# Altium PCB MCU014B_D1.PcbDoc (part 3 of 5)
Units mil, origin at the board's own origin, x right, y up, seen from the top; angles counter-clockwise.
Board outline 2300.04 x 4058 mil, 4 copper layers (TOP, GND, PWR, BOTTOM), stack 48.84 mil thick; 371 components, 238 nets, 1148 pads, 688 vias.
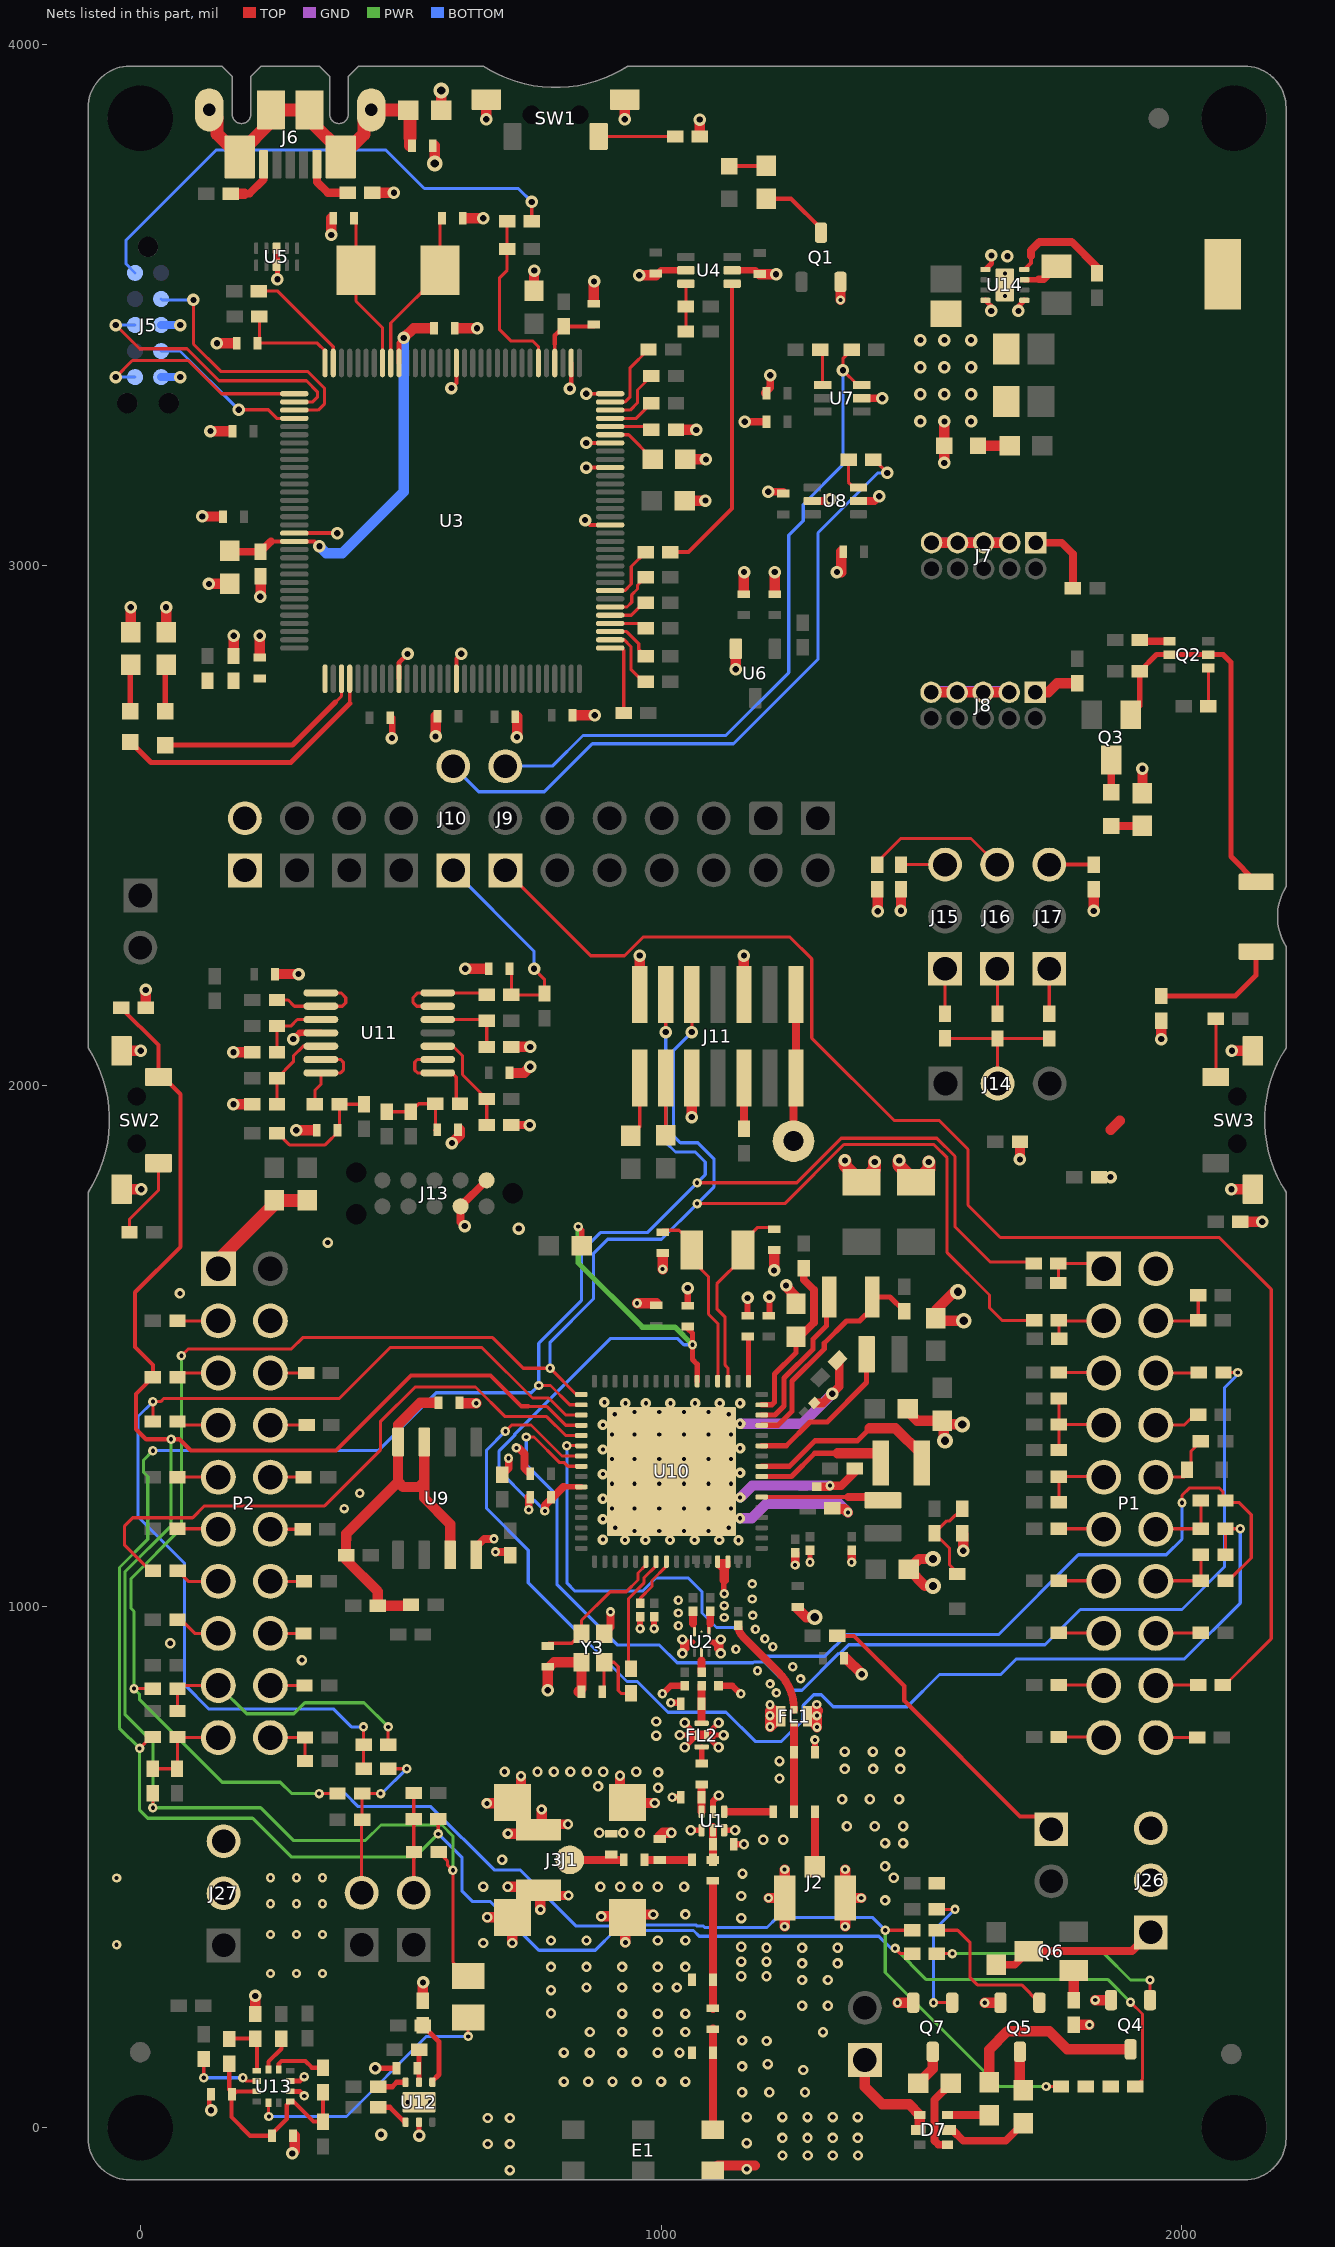
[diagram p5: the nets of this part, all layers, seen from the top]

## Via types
v1: diameter 24, hole 12, TOP to BOTTOM, tented both sides, 230 vias
v2: diameter 18, hole 8, TOP to BOTTOM, tented both sides, 218 vias
v3: diameter 20, hole 10, TOP to BOTTOM, tented both sides, 159 vias
v4: diameter 19.68, hole 7.87, TOP to BOTTOM, 32 vias
v5: diameter 20, hole 8, TOP to BOTTOM, tented both sides, 24 vias
v6: diameter 30, hole 16, TOP to BOTTOM, tented both sides, 17 vias
v7: diameter 20, hole 8, TOP to BOTTOM, tented bottom, 4 vias
v8: diameter 19.68, hole 7.87, TOP to BOTTOM, tented bottom, 4 vias

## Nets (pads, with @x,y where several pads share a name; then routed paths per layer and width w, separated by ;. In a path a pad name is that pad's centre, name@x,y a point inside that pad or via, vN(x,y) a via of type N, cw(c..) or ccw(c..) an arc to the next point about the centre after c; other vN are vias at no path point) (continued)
GND: C3.2 C4.2 C5.2 C8.2 C11.2 C14.2 C15.2 C17.2 C18.2 C19.2 C20.2 C21.1 C22.2 C23.1 C24.2 C25.2 C26.2 C27.2 C28.2 C29.2 C30.2 C31.2 C32.2 C33.2 C34.2 C35.2 C36.2 C37.2 C38.2 C39.2 C40.2 C41.2 C42.2 C43.2 C44.2 C45.2 C46.2 C47.2 C48.2 C49.2 C50.2 C51.2 C52.2 C53.2 C54.2 C55.2 C56.2 C57.2 C58.2 C59.2 C60.2 C61.2 C62.2 C63.2 C64.2 C65.2 C66.2 C67.2 C68.2 C69.2 C70.2 C71.2 C72.2 C73.2 C74.2 C75.2 C76.2 C77.2 C78.2 C79.2 C80.2 C81.2 C82.2 D8.1 E1.1 E1.6 FL1.2 FL1.4 FL2.2 J1.2 J1.3 J1.4 J1.5 J2.2@1353.38,440.99 J2.3@1237.23,440.99 J3.2@764.84,456.14 J3.3@764.84,572.28 J5.3 J5.5 J7.3 J7.5 J7.7 J7.9 J8.3 J8.5 J8.7 J8.9 J11.5 J11.10 J11.13 J13.1 J13.9 J26.2 J26.3 J27.2 J27.3 J28.1 J28.2 L1.2 L2.2 L3.1 L3.2 L4.1 L6.2 P1.2 P2.4 Q1.2 Q4.2 Q5.2 Q7.2 R16.1 R18.1 R19.1 R21.1 R25.1 R27.1 R30.1 R45.2 R46.2 R56.2 R57.2 R58.2 R59.2 R62.2 R63.2 R118.1 R119.1 R128.1 R129.1 R140.1 R144.1 R156.2 R157.2 R158.1 R159.1 R169.2 R170.2 R171.2 R172.1 SW1.1 SW1.2 SW2.1 SW2.2 SW3.1 SW3.2 TP2.1 U1.2 U1.4 U1.6 U2.2 U3.10 U3.17 U3.48 U3.55 U3.58 U3.64 U3.66 U3.80 U3.114 U4.2 U4.5 U5.3@261.87,3608.55 U5.8@261.87,3575.68 U6.2 U7.2 U8.2 U8.5 U9.4 U10.29 U10.30 U10.65@1020,1260 U11.11 U12.2 U12.7@535.13,48.96 U13.8 U13.9 U14.1 U14.4 U14.5 U14.9@1660,3538 Y3.2 Y3.4 | length 9418.8
  TOP w6: v1(856.09,3329.09) U3.64@902.15,3329.09
  TOP w7.5: U3.114@295.85,3061.38 v1(378.38,3061.38) ; v1(597.5,3340) 606.87,3349.37 U3.80@606.87,3388.15 ; U3.17@606.87,2781.85 606.87,2820.63 v1(616.24,2830) ; v1(854,3086.5) 863.37,3077.13 U3.48@902.15,3077.13
  TOP w8: C77.2@132.38,64.62 132.38,37.24 v1(136,33.62) ; v1(856.09,3187.36) U3.55@902.15,3187.36 ; v1(856.09,3234.61) U3.58@902.15,3234.61
  TOP w9: U3.10@496.64,2781.85 496.64,2812.72 v1(513.33,2829.41) ; v1(825,3339) 827.35,3341.35 U3.66@827.35,3388.15
  TOP w10: U5.3@261.87,3608.85 263.37,3607.35 v1(263.37,3548.7) ; U13.8@288.09,69.78 306.16,69.78 v2(314.75,61.18) ; U13.9@288.09,89.46 306.16,89.46 v2(314.75,98.06) ; v1@451.39,114.17 C75.2@488.19,114.17 ; v1@535.13,-14.51 U12.2@535.13,10.58 ; U10.65@1020,1260 U10.65@1060.07,1260 ; v3(1035.72,753.95) 1056.53,753.95 ; v3(1045.23,730.26) 1056.61,741.64 ; v3(1045.23,777.49) 1056.61,766.11 ; v3(1056.95,571.21) U1.4@1077.81,571.21 ; 1060.99,932.29 1055.82,932.29 ; 1094.62,932.29 1099.79,932.29 ; v3(1110.38,730.26) 1099,741.64 ; v3(1110.38,777.49) 1099,766.11 ; v3(1119.89,753.79) 1099.08,753.79 1099,753.87 ; v2@1120.3,1026.4 1120.3,1044.53 ; U1.6@1121.11,571.21 v3(1141.97,571.21) ; v2(1285.88,1085.78) C55.2@1285.88,1108.75 ; U14.4@1622.6,3508.47 1634,3497.07 v1(1634,3488) ; U14.1@1622.6,3567.53 1634.17,3579.09 v1(1634.17,3594.56) ; v1(1686,3488) 1686,3497.07 U14.5@1697.4,3508.47 ; 1055.82,932.29 1045.97,932.29 v3(1040.92,937.34) v3(1040.92,910.62) 1049.27,918.97 1049.27,925.75 1055.82,932.29 ; 1056.61,741.64 FL2.2@1068.85,753.87 ; 1056.61,741.64 1056.61,753.87 ; 1056.61,753.87 1056.61,766.11 ; 1056.61,753.87 FL2.2@1068.85,753.87 ; 1056.61,766.11 FL2.2@1068.85,753.87 ; FL2.2@1086.76,753.87 1099,753.87 ; FL2.2@1086.76,753.87 1099,741.64 ; FL2.2@1086.76,753.87 1099,766.11 ; 1099,741.64 1099,753.87 ; 1099,753.87 1099,766.11 ; 1099.79,932.29 1109.64,932.29 v3(1114.69,937.34) v3(1114.69,910.62) 1106.34,918.97 1106.34,925.75 1099.79,932.29 ; U10.29@1108.58,1080.29 1116.82,1072.06 1116.82,1050.42 1121.18,1046.05 1125.38,1050.24 1125.38,1074.58 1128.27,1077.47 U10.30@1128.27,1080.29 ; U10.29@1108.58,1080.29 U10.29@1108.58,1086.77 U10.30@1128.27,1086.77 U10.30@1128.27,1080.29 ; U10.29@1108.58,1080.29 U10.30@1128.27,1080.29
  TOP w12: v1(294,2090) 306,2102 U11.11@346.8,2102 ; v1(483.24,2668) 483.62,2668.38 C35.2@483.62,2707 ; v2(959.69,958.27) C64.2@959.69,981.27 ; v2(986.58,958.27) C54.2@986.58,981.27 ; C19.2@990,3556.38 999.62,3566 U4.2@1047.71,3566 ; v2(1002.48,833.2) 1003.19,833.2 1018.71,848.72 C15.2@1045.31,848.72 ; v2(1018.73,816.03) 1035.75,816.03 L4.1@1037.81,813.97 ; v2(1021.45,634.5) L2.2@1037.81,634.5 ; C47.2@1051,1581.62 v1(1051,1612) ; U1.2@1099.46,606.65 1099.46,626.63 v3(1110.63,637.8) ; C14.2@1110.31,848.72 1136.91,848.72 v2@1152.42,833.2 ; U4.5@1136.29,3566 1181.38,3566 C18.2@1189,3558.38 ; C5.2@1139.46,544.06 v3(1159.16,544.06) ; C63.2@1166,1562.62 v1(1166,1593) ; C52.2@1207,1562.62 1208,1563.62 v1(1208,1595) ; L1.2@1295.31,721.28 v2(1295.3,744.64)
  TOP w15: E1.1@1099.46,-3.54 L3.1@1099.46,144.21 C8.2@1099.46,190.51
  TOP w15.01: v1(623,1731) 615,1739 J13.9@615,1769 J13.1@665,1819 ; U9.4@645,1099.95 645,1115.2 660.31,1130.51 v2(679.11,1130.51) ; v2(682.15,1105.46) 703.82,1105.46 R46.2@710.53,1098.76 ; R45.2@695,1253.62 707.53,1266.15 v2@707.53,1285.16 ; R128.1@712.62,1925 v1(748,1925) ; v2(722.24,1305.16) 726.39,1305.16 737.67,1293.87 737.67,1266.33 C60.2@746,1258 ; C48.2@745,1210 745.98,1209.02 v2(745.98,1186.3) ; Y3.4@890.51,948.7 902.91,961.1 v2(902.91,990.38) ; v1(1160.6,3275.41) C26.2@1198.98,3275.41 ; C28.2@1198.98,3330.41 1209.6,3341.03 v1(1209.6,3364.41) ; v1(1205.6,3141.03) C40.2@1234.6,3141.03 ; U8.5@1290.42,3123.41 1322.02,3123.41 v1(1325.02,3126.41) ; U8.2@1379,3123.41 1409.6,3123.41 v1(1418.6,3132.41) ; U7.2@1385,3320.41 v1(1424.6,3320.41)
  TOP w16.54: v2(1257.24,1080.39) C68.2@1257.24,1103.75 ; C46.2@1294.06,1391.37 1310.61,1391.37 v1(1328.37,1409.13) 1342.19,1422.96 1342.19,1470.24 C45.2@1339.03,1473.41 ; C44.2@1298.78,1230.47 1321.97,1230.47 v2(1324.35,1232.86) 1346.24,1232.86 1371.54,1258.15 C43.2@1371.54,1265.69 ; v2(1365.68,1085.78) C53.2@1365.68,1108.75
  TOP w17.72: 1218.58,778.37 FL1.4@1229.71,789.51 1218.58,800.64 ; 1292.03,778.37 FL1.2@1280.9,789.51 1292.03,800.64
  TOP w18: J3.2@764.84,456.14 770.7,450.28 775.06,445.92 778.7,449.56 782.44,445.82 v3(822.17,445.82) ; J3.3@770.5,582.44 v3(821.18,582.44) ; FL2.2@1068.85,753.87 FL2.2@1086.76,753.87
  TOP w19.68: E1.6@1099.46,-82.28 1109.35,-72.4 1180.11,-72.4
  TOP w19.9: C71.2@262.62,2215 v1(304,2215) ; v1(624,2225) C72.2@665.38,2225 ; v1(782.17,839.98) 782.17,881.38 794.37,893.58 Y3.2@847.2,893.58 847.2,842.83 C67.2@841.38,837 ; v2(1003,1648.33) C65.2@1003,1675.71 ; v1(1217,1646) C66.2@1217,1681.38 ; v1(1240,1617) 1240,1614.43 1259,1595.43 C62.2@1259,1581.5 ; C42.2@1328.62,1189.5 1330.29,1187.83 1352.22,1187.83 v2(1358.78,1181.27) ; C49.2@1354.69,901.65 1385.02,871.32 v1(1385.02,870.65) ; R57.2@1415,2377.76 1415.91,2376.85 v1(1415.91,2335.47) ; v1(1460.5,2336.5) R56.2@1460.5,2377.88 ; v6(1522,1040) 1507.5,1040 C51.2@1475.5,1072 1495.5,1092 v6(1522,1092) ; C57.2@1543,1354.5 1543,1321 v6(1545,1319) ; v1(1543.73,3196.14) 1543.52,3196.36 D8.1@1543.52,3229 1543.52,3275.52 v1(1544,3276) ; v6(1570,1605) 1563,1605 1527,1569 C59.2@1527,1554.5 1532.5,1549 v6(1581,1549) ; v1(1830.63,2336.17) R58.2@1830.63,2377.54
  TOP w20: SW2.2@-35.88,1801.72 v1(1.72,1801.72) ; SW2.1@-35.88,2067.47 v1(0.96,2067.47) ; v1(-18.38,2919.38) -18,2919 R18.1@-18,2871.5 ; R156.2@10.62,2150 v1(10.62,2184.38) ; v1(49.62,2919.38) 50,2919 R19.1@50,2871.5 ; v1(119.25,3093.38) 155,3093.38 C30.2@155.38,3093 ; v1(132,2963.87) 171.37,2963.87 C38.2@172,2964.5 ; v1(134.76,3257.38) 173.38,3257.38 C31.2@173.76,3257 ; v1(147.21,3426.21) C17.2@181.59,3426.21 ; v1(179,1965) R129.1@215.38,1965 ; v1(179,2065) R118.1@215.38,2065 ; R16.1@179,2825.62 179.38,2826 v1(179.38,2864.62) ; R140.1@221,218.24 v1(221,253) ; C20.2@229,2825.62 229.38,2826 v1(229.38,2864.62) ; v1(230.62,2939.38) 231,2939.76 C37.2@231,2978.38 ; v1(292,-49.38) 296.62,-44.76 C76.2@296.62,-15.38 ; v1(299.63,1915) C74.2@335.38,1915 ; v1(366.96,3634.02) C23.1@366.96,3665.83 ; L6.2@445.62,3715 v1(487,3715) ; R144.1@542.54,243.6 542.54,278.6 v1(542.92,278.98) ; v6(565.12,3771.12) C22.2@565.12,3805 ; v1(567,2671) 567,2709.62 C34.2@567.38,2710 ; R27.1@577.99,3873.35 v6(577.99,3911.36) ; v1(598.49,1890.44) 613.82,1905.77 C73.2@613.82,1915.96 ; C39.2@607.62,3455 608,3454.62 v1(646.62,3454.62) ; C50.2@616.5,1392.1 617.6,1391 v2(645,1391) ; C21.1@622.95,3665.91 v1(658.7,3665.91) ; v1(664.5,3856.15) SW1.2@664.5,3893.88 ; v3(665.66,622.56) 712.74,622.56 J1.2@714.64,624.45 731.07,640.88 731.02,640.93 v3(731.02,675.07) ; v3(666.08,404.16) 712.53,404.16 713.49,405.12 J1.3@714.64,403.98 714.19,403.53 714.32,403.41 v3(714.32,354.55) ; v3(705.49,462.75) 758.01,462.75 758.12,462.86 J3.2@764.84,456.14 ; v3(705.92,564.67) 757.22,564.67 J3.3@764.84,572.28 ; C70.2@712.62,2025 737,2025 v1(749,2037) ; R119.1@712.62,2075 v1(749,2075) ; v1(723.24,2670) 723.62,2670.38 C36.2@723.62,2709 ; C32.2@756,3526.5 756,3565.12 v1(756.38,3565.5) ; v3(768.35,418.72) 768.35,447.93 J3.2@770.7,450.28 ; J3.3@770.5,582.44 v3(770.5,611.01) ; C29.2@833.62,2712 834,2711.62 v1(872.62,2711.62) ; C27.2@871,3505.62 871,3544.24 v1(871.38,3544.62) ; v3(884.95,405.78) 933.3,405.78 J1.4@935.11,403.98 ; v3(921.02,675.8) 921.02,639.08 920.75,638.81 J1.5@935.11,624.45 936.56,623 936.91,623.35 v3(987.96,623.35) ; v1(930.25,3856.15) SW1.1@930.25,3893.88 ; v3(931.57,355.78) 931.57,400.44 J1.4@935.11,403.98 ; v2(954,1583) 954.38,1582.62 C61.2@991,1582.62 ; v1(958.19,3556.38) C19.2@990,3556.38 ; J11.13@959,2175.43 v1(959,2250.35) ; v3(984.74,409.41) 940.78,409.41 940.66,409.52 J1.4@935.11,403.98 ; C3.2@997,557.14 997,559.43 1003.68,566.1 v3(1019.84,566.1) ; R25.1@1028.62,3260 1029,3259.62 v1(1067.62,3259.62) ; C33.2@1045.5,3124 v1(1085.18,3124) ; R30.1@1046.5,3203 v1(1086.18,3203) ; v1(1059,1940.28) J11.10@1059,2015.2 ; R21.1@1074.24,3823.02 v1(1074.24,3855.39) ; v1(1143.22,2800.24) 1143.22,2838.87 U6.2@1143.6,2839.24 ; J11.5@1159,2175.43 v1(1159,2250.35) ; C24.2@1159,2947.62 1159,2986.24 v1(1159.38,2986.62) ; C18.2@1189,3558.38 v1(1220.81,3558.38) ; v2(1206.23,440.99) J2.3@1237.23,440.99 ; v2@1209.19,799.73 v2(1209.19,791.25) ; C25.2@1218,2947.62 1218.38,2948 v1(1218.38,2986.62) ; 1218.58,778.37 1209.95,769.75 v2(1209.19,769.75) v2(1209.19,791.25) ; 1218.58,800.64 v2(1209.19,791.25) ; v2(1237.23,386.31) J2.3@1237.23,440.99 ; v2(1237.23,495.67) J2.3@1237.23,440.99 ; C58.2@1262.64,996.17 1278.6,980.21 v6(1295.31,980.21) ; 1292.03,778.37 v2@1299.26,771.14 ; 1292.03,800.64 1300.51,800.64 1297.62,797.75 1299.26,796.1 v2@1299.26,771.14 ; v2(1299.26,769.16) v2@1299.26,771.14 ; v1(1337.55,2986.71) 1345.9,2986.71 1345.98,2986.79 C41.2@1345.98,3025.41 ; v2(1344.4,3509.02) Q1.2@1344.4,3543.76 ; v2(1353.38,386.31) J2.2@1353.38,440.99 ; v2(1353.38,495.67) J2.2@1353.38,440.99 ; v2(1384.38,440.99) J2.2@1353.38,440.99 ; v2(1453.86,240.07) Q7.2@1484.09,240.07 ; C56.2@1473.5,1380 1473.5,1376 1491.99,1357.5 C57.2@1534,1357.5 ; J8.9@1518.28,2755.78 J8.7@1568.28,2755.78 J8.5@1618.28,2755.78 J8.3@1668.28,2755.78 ; J7.9@1519.19,3043.01 J7.7@1569.19,3043.01 J7.5@1619.19,3043.01 J7.3@1669.19,3043.01 ; R59.2@1578,1141.38 1580.02,1139.36 v1(1580.02,1107.83) ; v6(1578.43,1350.19) 1547.31,1350.19 1543,1354.5 C57.2@1542.5,1355 ; v2(1621.26,240.07) Q5.2@1651.49,240.07 ; v1(1689.04,1858.97) R62.2@1689.04,1892.69 ; R172.1@1792.2,197.45 v2(1822.44,197.45) ; v2(1833.66,245.07) Q4.2@1863.9,245.07 ; 1862.98,1915.62 1880.7,1933.35 ; R158.1@1924.21,2562.24 v1(1924.21,2609.21) ; v1(1960.07,2090.07) R159.1@1960.07,2125.59 ; v1(2095.06,1801.72) SW3.1@2135.88,1801.72 ; v1(2095.96,2067.47) SW3.2@2135.88,2067.47 ; R157.2@2112.26,1739.21 v1(2154.21,1739.21) ; C57.2@1534,1357.5 C57.2@1540,1357.5 C57.2@1542.5,1355 ; C57.2@1534,1357.5 1537.5,1354 1538.5,1355 C57.2@1542.5,1355
  TOP w25: v1(1353,1857.17) 1353,1847.09 C82.2@1385,1815.09 1410,1840.09 v1(1410,1854.17) ; v1(1457,1857.17) 1457,1847.09 C81.2@1489,1815.09 1514,1840.09 v1(1514,1854.17)
  GND w19.9: v5(1151.49,1170.12) 1174.12,1170.12 1201.6,1197.6 1342.45,1197.6 v2(1358.78,1181.27) ; v5(1151.7,1209.9) 1174.66,1232.86 v2(1324.35,1232.86) ; v5(1151.7,1351.63) 1270.87,1351.63 v1(1328.37,1409.13)
  GND w20: J7.9@1519.19,3043.01 J7.7@1569.19,3043.01 J7.5@1619.19,3043.01 J7.3@1669.19,3043.01 ; J8.9@1522.5,2757.61 J8.3@1672.5,2757.61
  BOTTOM w15: J5.5@40,3361 v1(77,3361) ; J5.3@40,3461 v1(77,3461)
  other v1: 535.69,-15.07 462.26,-13.27 451.35,114.22 726.56,1726.29 1862.98,1825.22 1498,3276 1595,3276 1498,3328 1544,3328 1595,3328 1498,3380 1544,3380 1595,3380 1498,3432 1544,3432 1595,3432 1665,3593
  other v2: 250,296 300,296 350,296 -45.44,351.28 250,371 300,371 350,371 250,430 300,430 350,430 -45.44,479.33 250,480 300,480 350,480 1299.03,791.12 1209.19,812.14 1298.88,812.42 1153.13,833.2 1221.31,834.82 1209.36,852.15 1267.85,861.76 1185.2,877.22 1252.9,884.97 1143.65,918.72 1214.58,923.42 1199.21,938.92 1181.07,956.9 1033.24,963.58 1121.41,979.63 1175.91,983.62 1033.24,988.2 1121.41,1002.46 1033.24,1012.82 1175.01,1015.04 1121.41,1025.29 1174.92,1044.06 391.67,1188.58 421.29,1218.21 707.05,1285.16
  other v3: 709.76,-81.3 1164.53,-79.52 1233.14,-53.39 1281.42,-53.39 1329.71,-53.39 1377.99,-53.39 667.01,-31.3 709.76,-31.3 1164.53,-29.52 1232.81,-19.52 1281.1,-19.52 1329.38,-19.52 1377.66,-19.52 667.01,18.7 709.76,18.7 1164.53,20.48 1232.81,20.48 1281.1,20.48 1329.38,20.48 1377.66,20.48 1155.53,68.01 1208,68.01 1276.28,68.01 813.41,88.46 860.06,88.46 906.72,88.46 953.37,88.46 1000.03,88.46 1046.68,88.46 1272.96,110.84 1155.53,117.72 1204.85,122.1 813.41,144.21 863.41,144.21 925.11,144.21 993.4,144.21 1035.31,144.21 1202.52,166.45 1155.53,167.43 863.41,183.82 925.11,183.82 993.4,183.82 1046.68,183.82 1310.83,183.63 1153.4,215.58 925.11,219.04 993.4,219.04 1046.68,219.04 788.55,219.71 1270.6,234.02 1320.18,234.02 788.55,264.21 856.83,269.21 925.11,269.21 993.4,269.21 1030.31,269.21 1270.6,283.6 1320.18,283.6 1154.04,290.6 1202.32,290.6 788.55,308.72 856.83,308.72 925.11,308.72 993.4,308.72 1046.68,308.72 1270.6,315.45 1338.89,315.45 1154.04,318.95 1202.32,318.95 1202.32,345.31 1270.6,345.31 1338.89,345.31 1154.04,347.31 658.58,354.55 788.55,359.48 856.83,359.48 993.4,359.48 1046.68,359.48 1154.04,402.5 1046.68,409.52 1430.08,436.31 1154.04,444.8 658.58,462.86 883.54,462.82 921.45,462.82 955.55,462.82 993.4,462.82 1044.07,462.82 1446.72,480.06 1156.25,487.84 1430.08,502.07 694.67,514.52 1430.08,546.35 1464.62,546.35 1196.16,552.92 1234.44,552.92 881.1,566.1 927.65,566.1 959.36,566.1 1356.8,578.69 1410.08,578.69 1464.62,578.69 1347.58,630.42 1400.86,630.42 1456.93,630.42 994.19,652.57 879.05,655.59 1227.26,670.52 994.19,682.15 699.45,683.36 762.68,683.36 794.29,683.36 825.91,683.36 857.52,683.36 889.14,683.36 952.36,683.36 1352.52,688.93 1407.1,688.93 1459.18,688.93 1227.26,703.77 1352.52,722.12 1406.72,722.12 1459.18,722.12 990.71,752.76 990.71,779.83 310.32,897.8 57.42,930.29 76.25,1601.77 360.12,1699.33
  other v4: 949.13,1145.83 996.38,1145.83 1043.62,1145.83 1090.87,1145.83 905.83,1189.13 949.13,1189.13 996.38,1189.13 1043.62,1189.13 1090.87,1189.13 1134.17,1189.13 905.83,1236.38 949.13,1236.38 996.38,1236.38 1043.62,1236.38 1090.87,1236.38 1134.17,1236.38 905.83,1283.62 949.13,1283.62 996.38,1283.62 1043.62,1283.62 1090.87,1283.62 1134.17,1283.62 905.83,1330.87 949.13,1330.87 996.38,1330.87 1043.62,1330.87 1090.87,1330.87 1134.17,1330.87 949.13,1374.17 996.38,1374.17 1043.62,1374.17 1090.87,1374.17
  other v5: 930.66,1128.3 969.9,1128.3 1017.14,1128.3 1064.39,1128.3 1111.63,1128.3 1148.67,1127.77 888.3,1129.12 888.3,1168.37 888.3,1207.61 888.3,1254.86 1151.7,1257.14 888.3,1302.1 1151.7,1304.39 888.3,1349.34 931.48,1390.88 970.72,1390.88 1017.97,1390.88 1065.21,1390.88 1112.46,1390.88 1151.7,1390.88 891.25,1392.67
  other v7: 911.89,1151.89 1129.9,1151.89 910.9,1369.9 1129.9,1369.9
  other v8: 513.48,48.96 556.79,48.96 1660,3516.35 1660,3559.65
IRSTN: J5.10 R29.1 | length 999.4
  TOP w6: R29.1@751.62,3660 v1(751.62,3697.38)
  BOTTOM w6: J5.10@-10,3561 -27.43,3578.43 -27.43,3623.68 145.88,3796.99 471.54,3796.99 545.41,3723.12 725.88,3723.12 v1(751.62,3697.38)
ITCK: J5.4 U3.100 | length 309.3
  TOP w6: v1(189.21,3298.21) 245.7,3298.21 262.07,3281.85 U3.100@295.85,3281.85
  BOTTOM w6: J5.4@40,3411 76.43,3411 v1(189.21,3298.21)
ITDI: J5.8 U3.98 | length 535.9
  TOP w6: v1(-47,3461) -1.41,3415.41 89.75,3415.41 151.17,3354 319.2,3354 340,3333.2 340,3322 331.35,3313.35 U3.98@295.85,3313.35
  BOTTOM w6: v1(-47,3461) J5.8@-10,3461
ITDO: J5.6 U3.97 | length 419.5
  TOP w6: v1(-47,3361) -15.05,3392.95 92.02,3392.95 155.88,3329.09 U3.97@295.85,3329.09
  BOTTOM w6: v1(-47,3361) J5.6@-10,3361
ITMS: J5.2 U3.99 | length 527.3
  TOP w6: v1(102.21,3509.21) 102.21,3424.21 154.43,3372 321,3372 354,3339 354,3310 341.6,3297.6 U3.99@295.85,3297.6
  BOTTOM w6: J5.2@40,3511 41.79,3509.21 v1(102.21,3509.21)
LED0: D1.2 U3.3 | length 410.7
  TOP w6: 375,2737 386.4,2748.4 U3.3@386.4,2781.85
  TOP w10: D1.2@48,2654.52 292.52,2654.52 375,2737
LED1: D2.1 U3.4 | length 532.1
  TOP w6: 402.15,2734.15 U3.4@402.15,2781.85
  TOP w10: D2.1@-19,2660.47 20.47,2621 289,2621 402.15,2734.15
LP_GPIO_01: J9.1 R91.2 | length 2785.7
  TOP w6: J9.1@701,2414 865,2250 929.74,2250 965.78,2286.04 1247.28,2286.04 1289.21,2244.11 1289.21,2091.79 1447.05,1933.95 1533.48,1933.95 1589.21,1878.23 1589.21,1771.3 1651.3,1709.21 2071.86,1709.21 2171.45,1609.62 2171.45,938.92 2082.53,850 R91.2@2078.62,850
LP_GPIO_02: C72.1 J10.1 R112.1 R116.2 | length 423.3
  TOP w6: C72.1@712.62,2225 R116.2@712.62,2175 773.38,2175 R112.1@776,2177.62 776,2205 v1(756,2225)
  BOTTOM w6: J10.1@601,2414 756,2259 v1(756,2225)
LP_RESET_OUT: D5.2 P1.10 R152.2 | length 136.2
  TOP w6: P1.10@1949.91,1249 2003.41,1249 2017.41,1263 2017.41,1299.03 R152.2@2036.38,1318
NetC1_1: C1.1 FL1.3 L1.1 R2.2 | length 168.2
  TOP w15: R2.2@1255.31,606.65 L1.1@1255.31,721.28 FL1.3@1255.31,774.85
NetC1_2: C1.2 J2.1 | length 105.6
  TOP w15: J2.1@1295.31,501.03 C1.2@1295.31,606.65
NetC2_1: C2.1 C3.1 R3.2 | length 85.6
  TOP w15: C2.1@972.81,514.21 C3.1@997,514.21 R3.2@1058.39,514.21
NetC2_2: C2.2 C4.1 J1.1 J3.1 | length 105.6
  TOP w15: J1.1@816.11,514.21 J1.1@824.87,514.21 C2.2@921.72,514.21
NetC5_1: C5.1 R3.1 R4.1 U1.5 | length 63.1
  TOP w15: R4.1@1099.46,514.21 C5.1@1099.46,544.06 U1.5@1099.46,577.28
NetC6_1: C6.1 FL2.1 L4.2 | length 68.9
  TOP w15.75: FL2.1@1077.81,779.8 L4.2@1077.81,813.97 C6.1@1077.81,848.72
NetC6_2: C6.2 U2.5 | length 38.2
  TOP w6: 1077.79,896.92 U2.5@1077.81,912.93
  TOP w15: C6.2@1077.81,874.7 1077.79,896.92
NetC7_1: C7.1 FL2.3 | length 30.9
  TOP w10.59: C7.1@1077.81,699.21 FL2.3@1077.81,730.15
NetC7_2: C7.2 L2.1 U1.3 | length 51.6
  TOP w15: U1.3@1077.81,606.65 L2.1@1077.81,634.5 C7.2@1077.81,658.26
NetC8_1: C8.1 C11.1 R4.2 | length 244.5
  TOP w15: C8.1@1099.46,227.91 C11.1@1099.46,284.21 R4.2@1099.46,472.4
NetC9_1: C9.1 U2.3 | length 39.9
  TOP w6: 1060.65,968.48 1061.3,967.84 1064.03,965.11 U2.3@1064.03,952.3
  TOP w15: 1061.3,967.84 C9.1@1061.3,990.19
NetC10_1: C10.1 U2.1 | length 39.9
  TOP w6: U2.1@1091.58,952.3 1091.58,965.11 1094.31,967.84 1094.96,968.48
  TOP w15: 1094.31,967.84 C10.1@1094.31,990.19
NetC17_1: C17.1 R8.2 U3.96 | length 206.3
  TOP w6: R8.2@228.83,3477.21 228.83,3426.21 339.79,3426.21 354.91,3411.09 U3.96@354.91,3388.15
NetC20_1: C20.1 R15.2 R16.2 U3.1
NetC21_2: C21.2 U3.88 Y1.2 | length 317
  TOP w6: U3.88@480.89,3388.15 480.89,3464.89 575.71,3559.71 C21.2@575.71,3665.91
NetC22_1: C22.1 J6.6 J6.7 J6.8 J6.9 J6.10 J6.11 R27.2 | length 674.9
  TOP w22: C22.1@517.87,3805 517.87,3819.87
  TOP w25: J6.10@133.25,3874.12 147.67,3859.7 147.67,3827.71 191.82,3783.57 191.82,3791.83 251.85,3851.87 251.85,3874.12 325.67,3874.12 325.67,3853.55 385.71,3793.51 385.71,3783.57 429.31,3827.16 429.31,3859.15 444.28,3874.12 514.24,3874.12 R27.2@515,3873.35 517.87,3870.48 517.87,3819.87
NetC23_2: C23.2 U3.89 Y1.1 | length 298.8
  TOP w6: C23.2@414.2,3665.83 414.29,3665.74 Y1.1@414.29,3566 414.29,3506.85 465.14,3456 U3.89@465.14,3388.15
NetC27_1: C27.1 R32.2 U3.68 | length 135.3
  TOP w7.5: U3.68@795.85,3388.15 795.85,3424.85
  TOP w8: 795.85,3424.85 795.85,3441.23 R32.2@813,3458.38 C27.1@871,3458.38
NetC37_1: C37.1 C38.1 C39.1 U3.87 U3.115 | length 810.6
  TOP w7.5: 251.25,3045.63 U3.115@295.85,3045.63 334.63,3045.63 v1(344,3036.26)
  TOP w9: U3.87@496.64,3388.15 496.64,3426.93 v1(506.01,3436.3)
  TOP w15.01: C38.1@172,3027.5 173.87,3025.62 C37.1@231,3025.62 251.01,3045.63 251.25,3045.63
  TOP w20: v1(506.01,3436.3) 524.71,3455 C39.1@560.38,3455
  BOTTOM w20: v1(344,3036.26) 357.11,3023.15 388.09,3023.15 506.01,3141.08 v1(506.01,3436.3)
NetC47_1: C47.1 C48.1 R40.1 U10.10 U10.54 | length 1222.2
  TOP w10: 812.71,1230.47 U10.10@846.77,1230.47 ; v2(841,1730) 847.5,1723.5 R40.1@847.5,1693 ; C47.1@1051,1534.38 1060.21,1525.17 v2(1060.21,1503.21) 1060.21,1474.67 1069.21,1465.68 U10.54@1069.21,1433.23
  TOP w15.01: v2(776.82,1183.98) 776.82,1194.57 792.24,1210 812.71,1230.47
  PWR w10: v2(841,1730) 841,1660 964,1537 1026.43,1537 v2(1060.21,1503.21)
  BOTTOM w6: v2(776.82,1183.98) 756.24,1204.55 745.45,1204.55 689,1261 689,1299.55 719,1329.54 719,1331.29 901.71,1514 ; 901.72,1515 1032,1515 1043.79,1503.21 v2(1060.21,1503.21)
NetC50_1: C50.1 R42.1 R43.1 R44.1 U9.3 U9.7 U9.8 | length 835.4
  TOP w19.9: R43.1@519.76,1004 517.76,1002 R42.1@455.92,1002 455.92,1029.51 396,1089.43 396,1090 395.38,1090.62 R44.1@395.38,1099 395,1099.38 395,1129.43 395.32,1129.75 395.32,1140.32 495,1240 ; U9.7@545,1306.49 545,1240 ; C50.1@565.71,1392.1 537.1,1392.1 495,1350 U9.8@495,1316.49 495,1240 ; U9.3@595,1117.51 595,1159 545,1209 545,1240 ; 495,1240 505,1230 535,1230 545,1240
NetC62_1: C62.1 R48.1 U10.47 | length 327.9
  TOP w10: U10.47@1193.23,1387.95 1212.95,1387.95 1217.98,1392.98 1217.98,1446.98 1259,1488 C62.1@1259,1518.5
  TOP w15.01: C62.1@1259,1518.5 1266.5,1518.5 1293.35,1545.35 1293.35,1608.65 1274,1628 R48.1@1274,1650.38
NetC63_1: C63.1 U10.49 | length 82.8
  TOP w10: C63.1@1166,1515.38 1167.64,1513.74 U10.49@1167.64,1433.23
NetC64_1: C64.1 U10.24 | length 91.9
  TOP w6: C64.1@959.69,1007.25 959.69,1016.24 982.42,1038.97 982.42,1050.52 U10.24@1010.16,1078.26
NetC65_1: C65.1 U10.52 Y2.2 | length 352.2
  TOP w6: C65.1@1003,1722.95 1034.47,1722.95 1058.79,1698.64 Y2.2@1058.79,1685 1058.79,1666.21 1091,1634 1091,1562 1109,1544 1109,1433.62 U10.52@1108.58,1433.23
NetC66_1: C66.1 U10.51 Y2.1 | length 368.2
  TOP w6: U10.51@1128.27,1433.23 1128.3,1458.7 1123,1464 1123,1556 1107,1572 1107,1620 1157.21,1670.21 1157.21,1700.21 1185.62,1728.62 C66.1@1217,1728.62
NetC67_1: C67.1 R49.1 Y3.3 | length 162.6
  TOP w6: C67.1@888.62,837 C67.1@890.51,838.89 ; C67.1@890.51,837 C67.1@890.51,838.89 ; R49.1@942.12,833.78 923.4,833.78 917.66,839.51 917.66,885.53 909.61,893.58 Y3.3@890.51,893.58 C67.1@890.51,838.89
NetC69_1: C69.1 U10.22 Y3.1 | length 280.8
  TOP w6: C69.1@782.17,928.62 783.55,930 828.5,930 Y3.1@847.2,948.7 847.2,974.13 902.06,1028.99 933.14,1028.99 955.76,1051.61 955.76,1064.97 970.79,1080 U10.22@970.79,1086.77
NetC73_1: C73.1 R120.1 R122.2 R123.1 | length 150
  TOP w6: R120.1@473,1950.62 R123.1@519.21,1950.62 534.61,1966.02 566.51,1966.02 R122.2@566.58,1965.96 C73.1@566.58,1915.96
NetC74_1: C74.1 R121.1 R124.2 R125.1 | length 237.9
  TOP w6: R121.1@262.62,1909 264.43,1909 286.43,1887 355,1887 382.62,1914.62 382.62,1915 R124.2@382.62,1965 R125.1@429.64,1965
NetC75_1: C75.1 R130.1 U12.5 | length 62
  TOP w10: U12.5@535.43,87.65 535.43,114.17 R130.1@535.43,149.61
NetC76_1: C76.1 C77.1 R131.1 R137.2 R146.2 U13.3 U13.7 | length 459.2
  TOP w8: R137.2@171,123 171,73.24 C77.1@179.62,64.62 ; U13.3@223.91,69.78 184.78,69.78 C77.1@179.62,64.62 ; R146.2@351,68 351,12.24 332.38,12.24 294.53,50.09 U13.7@288.09,50.09 281.35,43.36 281.35,16.6 249.38,-15.38 211,-15.38 175.29,20.33 175.29,60.29 C77.1@179.62,64.62
NetD1_1: D1.1 R19.2 | length 89.9
  TOP w10: D1.1@48,2719.48 48,2806.5 R19.2@50,2808.5
NetD2_2: D2.2 R18.2 | length 89.4
  TOP w10: D2.2@-19,2719.53 -19,2807.5 R18.2@-18,2808.5
NetD3_1: D3.1 R20.2 | length 71.1
  TOP w8: D3.1@1131,3766.19 1201.7,3766.19 R20.2@1202,3766.5
NetD4_1: D4.1 R55.1 R59.1 | length 164.3
  TOP w6: D4.1@1569,1071.59 1562.72,1071.59 1553.58,1080.73 1553.58,1112.8 R55.1@1525,1141.38 1548.62,1165 1554.38,1165 R59.1@1578,1188.62
NetD6_1: D6.1 R158.2 | length 60
  TOP w15.01: D6.1@1864.21,2499.25 R158.2@1924.21,2499.25
NetD6_2: D6.2 Q3.3 | length 61.7
  TOP w15.01: D6.2@1864.21,2564.21 Q3.3@1864.21,2625.91
NetD7_2: D7.2 R164.2 | length 151.2
  TOP w15.01: D7.2@1549.92,-32.87 1532.87,-32.87 1525,-25 1525,53.5 R164.2@1556.5,85
NetD7_3: D7.3 D7.5 J25.1 | length 209.3
  TOP w19.9: J25.1@1391.23,130.06 1391.23,78.57 1424.92,44.88 1476.1,44.88 D7.5@1496.77,24.21 1496.77,-1.38 D7.3@1493.82,-4.33
NetD7_4: D7.4 R163.2 | length 164.6
  TOP w15.01: D7.4@1552.87,-4.33 1559.33,-4.33 1580,-25 1661.5,-25 R163.2@1695,8.5
NetD7_6: D7.6 R162.2 | length 80.1
  TOP w15.01: D7.6@1549.92,24.21 R162.2@1630,24.21
NetD8_2: D8.2 R160.2 | length 60.5
  TOP w20: D8.2@1608.48,3229 R160.2@1669.01,3229
NetFL1_1: FL1.1 R1.1 | length 201.2
  TOP w15: R1.1@1148.06,964.77 ccw(c1179.16,964.77) 1157.17,942.78 1225.36,874.59 cw(c1153.08,802.3) FL1.1@1255.31,802.3
NetJ6_1: J6.1 L5.1 | length 102.8
  TOP w15.01: 200,3713 209.52,3713 236.82,3740.3 J6.1@236.82,3768.63
  TOP w19.9: L5.1@173.62,3713 200,3713
NetJ6_5: J6.5 L6.1 | length 100.6
  TOP w15.75: J6.5@339.18,3768.63 339.18,3735.82 360,3715 L6.1@398.38,3715
NetJ7_1: J7.1 R31.2 | length 146.3
  TOP w15.1: J7.1@1719.19,3043.01 1769.31,3043.01 1790.61,3021.71 R31.2@1790.61,2955.63
NetJ8_1: J8.1 R35.2 | length 88.1
  TOP w20: J8.1@1718.28,2755.78 1743.13,2755.78 1760.73,2773.38 R35.2@1799.13,2773.38
NetJ9_3: J9.3 R33.2 U7.3 | length 1335.9
  TOP w6: R33.2@1365.98,3413.41 1349,3396.43 v1(1349,3374) 1377,3346 U7.3@1385,3346
  BOTTOM w6: J9.3@701,2614 791,2614 850,2673 1124.32,2673 1245,2793.69 1245,3057.32 1272.88,3085.2 1272.88,3116.4 1349,3192.52 v1(1349,3374)
NetJ10_3: J10.3 R36.1 | length 1286.8
  TOP w6: R36.1@1407.22,3202.41 1409.01,3202.41 v1(1434.3,3177.12)
  BOTTOM w6: J10.3@601,2614 650,2565 776,2565 868,2657 1139.03,2657 1301.21,2819.18 1301.21,3061.85 1416.48,3177.12 v1(1434.3,3177.12)
NetJ11_1: J11.1 J11.2 TP1.1 | length 272.6
  TOP w15.01: TP1.1@1254.21,1894.21 1254.21,2010.41 J11.2@1259,2015.2 J11.1@1259,2164.8
NetJ11_6: J11.6 R37.1 | length 97.5
  TOP w15.01: J11.6@1159,2015.2 1159,1918.05 R37.1@1159.21,1917.83
NetJ11_12: J11.12 R38.2 | length 109.7
  TOP w6: R38.2@1009,1905.5 J11.12@1009,2015.2
NetJ11_14: J11.14 R39.2 | length 117.7
  TOP w6: R39.2@942,1904.5 959,1921.5 J11.14@959,2015.2
NetJ12_1: J12.1 R41.1 | length 581.3
  TOP w8: R41.1@1338.01,944.25 1370.59,944.25 1466.82,848.03 1466.82,819.87 1689.06,597.63 1724.37,597.63 J12.1@1749,573
NetJ14_2: J14.2 R51.1 R52.1 R53.1 | length 286.5
  TOP w6: R51.1@1545.12,2091.5 1545.45,2091.17 R52.1@1646.01,2091.17 ; J14.2@1646.01,2004.79 R52.1@1646.01,2091.17 ; R53.1@1745.12,2091.17 R52.1@1646.01,2091.17
NetJ15_1: J15.1 R51.2 | length 86.4
  TOP w6: R51.2@1545.12,2138.74 J15.1@1545.12,2225.12
NetJ15_3: J15.3 R56.1 | length 84.6
  TOP w6: R56.1@1460.5,2425.12 J15.3@1545.12,2425.12
NetJ16_1: J16.1 R52.2 | length 87.1
  TOP w6: J16.1@1645.12,2225.12 1646.01,2224.23 R52.2@1646.01,2138.41
NetJ16_3: J16.3 R57.1 | length 274.5
  TOP w6: R57.1@1415,2425 1415,2430 1460.12,2475.12 1595.12,2475.12 J16.3@1645.12,2425.12
NetJ17_1: J17.1 R53.2 | length 86.7
  TOP w6: R53.2@1745.12,2138.41 J17.1@1745.12,2225.12
NetJ17_3: J17.3 R58.1 | length 85.6
  TOP w8: J17.3@1745.12,2425.12 1830.3,2425.12 R58.1@1830.63,2424.79
NetJ19_2: J19.2 R132.2 R135.2 R136.2 | length 331.7
  TOP w6: J19.2@425,451 425,590.52 R135.2@426,591.52 R132.2@426,641.52 v2(461.52,641.52) ; R136.2@476,689.21 v2(511.52,689.21)
  BOTTOM w6: v2(461.52,641.52) 463.83,641.52 v2(511.52,689.21)
NetJ20_2: J20.2 R139.2 R142.2 R143.2 | length 191.5
  TOP w6: J20.2@525,451 R139.2@525,592.52 R142.2@525,642.52
NetJ26_1: J26.1 Q6.3 R166.1 | length 321.9
  TOP w15.01: R166.1@1643.9,312.73 1679.09,312.73 Q6.3@1705.59,339.23 1904.23,339.23 J26.1@1940,375
NetL7_2: L7.2 U10.38 | length 235.4
  TOP w8: U10.38@1193.23,1210.79 1359.41,1210.79
  TOP w15.01: 1359.41,1210.79 1419.58,1210.79 L7.2@1426,1204.37
NetL9_1: L9.1 U10.41 | length 374.9
  TOP w10: U10.41@1193.23,1269.84 1246.62,1269.84 1295.78,1319 1376.99,1319 1400.99,1343
  TOP w20: 1400.99,1343 1450,1343 1500.37,1292.63 L9.1@1500.37,1276
NetL9_2: L9.2 U10.40 | length 268
  TOP w10: U10.40@1193.23,1250.16 1250.29,1250.16 1295.13,1295 1338.8,1295
  TOP w20: 1338.8,1295 1416.63,1295 L9.2@1416.63,1281 ; L9.2@1416.63,1276 L9.2@1416.63,1281 ; L9.2@1421.63,1276 L9.2@1416.63,1281
NetL10_2: L10.2 U10.43 | length 306.1
  TOP w10: U10.43@1193.23,1309.21 1240.21,1309.21 1286,1355 1319,1355 1394.63,1430.63 L10.2@1394.63,1485
NetL11_1: L11.1 U10.46 | length 281.2
  TOP w10: U10.46@1193.23,1368.27 1218.72,1368.27 1236.08,1385.62 1236.08,1439.14 1291.6,1494.66 1291.6,1513.65 1317.66,1539.71 L11.1@1317.66,1583
NetL11_2: L11.2 R47.2 U10.45 | length 440.5
  TOP w10: U10.45@1193.23,1348.58 1224.49,1348.58 1251.53,1375.62 1251.53,1433.37 1313.19,1495.04 1313.19,1506.06 1355.96,1548.83 1381.21,1548.83 1405.34,1572.95 L11.2@1405.34,1595 1439.38,1595 R47.2@1467,1567.38
NetL12_1: L12.1 U14.7 | length 72.2
  TOP w9.84: U14.7@1697.4,3547.84 1723.84,3547.84 1725,3549
  TOP w15.01: 1725,3549 1734.57,3549 L12.1@1759,3573.43
NetP1_1: P1.1 R60.2 R67.2 | length 132.2
  TOP w6: R60.2@1762.83,1622.31 R67.2@1762.83,1659.21 P1.1@1826.7,1659.21
  TOP w10: P1.1@1826.7,1659.21 1826.7,1672.21 P1.1@1845.08,1672.21
NetP1_3: P1.3 R61.2 R68.2 | length 120
  TOP w6: R61.2@1764.25,1514.63 R68.2@1764.25,1549.38 ; R68.2@1764.62,1549 P1.3@1849.91,1549
NetP1_4: P1.4 R65.1 R69.1 | length 129.9
  TOP w6: P1.4@1949.91,1549 2030.38,1549 R65.1@2031.38,1550 R69.1@2031.38,1598
NetP1_5: P1.5 R70.2 | length 86.7
  TOP w6: R70.2@1763.62,1450 1848.91,1450 P1.5@1849.91,1449
NetP1_6: P1.6 R71.1 | length 83
  TOP w6: P1.6@1949.91,1449 2031.46,1449 R71.1@2032.46,1450
NetP1_7: P1.7 R72.2 R102.2 R103.2 | length 185.7
  TOP w6: R103.2@1763.62,1301 R72.2@1763.62,1350 ; R102.2@1763.62,1400 R72.2@1763.62,1350 ; P1.7@1849.91,1349 1848.91,1350 R72.2@1763.62,1350
NetP1_8: P1.8 R73.1 | length 89.8
  TOP w6: P1.8@1949.91,1349 2004,1349 2024,1369 R73.1@2031.38,1369
NetP1_9: P1.9 R75.2 R107.2 | length 135.7
  TOP w6: R107.2@1763.62,1201 R75.2@1763.62,1250 1848.91,1250 P1.9@1849.91,1249
NetP1_11: P1.11 R78.2 | length 86.7
  TOP w6: R78.2@1763.62,1150 1848.91,1150 P1.11@1849.91,1149
NetP1_12: P1.12 R79.1 R104.1 | length 140.9
  TOP w6: P1.12@1949.91,1149 1950.91,1150 R79.1@2036.38,1150 R104.1@2036.38,1204
NetP1_13: P1.13 R82.2 | length 86.7
  TOP w6: R82.2@1763.62,1050 1848.91,1050 P1.13@1849.91,1049
NetP1_14: P1.14 R83.1 R105.1 | length 136.9
  TOP w6: P1.14@1949.91,1049 1950.91,1050 R83.1@2036.38,1050 R105.1@2036.38,1100
NetP1_15: P1.15 R86.2 | length 86.7
  TOP w6: R86.2@1763.62,950 1848.91,950 P1.15@1849.91,949
NetP1_16: P1.16 R87.1 | length 86.9
  TOP w6: P1.16@1949.91,949 1950.91,950 R87.1@2036.38,950
NetP1_17: P1.17 R90.2 | length 86.7
  TOP w6: R90.2@1763.62,850 1848.91,850 P1.17@1849.91,849
NetP1_18: P1.18 R91.1 | length 81.9
  TOP w6: P1.18@1949.91,849 1950.91,850 R91.1@2031.38,850
NetP1_19: P1.19 R94.2 | length 86.7
  TOP w6: R94.2@1763.62,750 1848.91,750 P1.19@1849.91,749
NetP1_20: P1.20 R95.1 | length 79.5
  TOP w6: P1.20@1949.91,749 R95.1@2029.38,748.99
NetP2_1: P2.1 R64.2 R66.2 | length 235
  TOP w25: P2.1@149.91,1649 149.91,1665.16 265.26,1780.5 R64.2@321,1780.5
NetP2_3: P2.3 R74.2 | length 78.3
  TOP w6: R74.2@71.62,1549 P2.3@149.91,1549
NetP2_5: P2.5 R76.2 | length 81.6
  TOP w6: R76.2@71.62,1441 79.62,1449 P2.5@149.91,1449
NetP2_6: P2.6 R77.1 | length 68.5
  TOP w6: P2.6@249.91,1449 R77.1@318.38,1449
NetP2_7: P2.7 R80.2 | length 81.2
  TOP w6: R80.2@71.62,1356 78.62,1349 P2.7@149.91,1349
NetP2_8: P2.8 R81.1 | length 69.5
  TOP w6: P2.8@249.91,1349 R81.1@319.38,1349
NetP2_9: P2.9 R84.2 | length 78.3
  TOP w6: R84.2@71.62,1249 P2.9@149.91,1249
NetP2_10: P2.10 R85.1 | length 63.6
  TOP w6: P2.10@249.91,1249 R85.1@313.49,1249.01
NetP2_11: P2.11 R88.2 | length 78.7
  TOP w6: R88.2@71.62,1150 148.91,1150 P2.11@149.91,1149
NetP2_12: P2.12 R89.1 | length 62.2
  TOP w6: P2.12@249.91,1149 311.98,1149 R89.1@312.09,1149.11
NetP2_13: P2.13 R92.2 | length 86.5
  TOP w6: R92.2@71.78,1069.21 91.99,1049 P2.13@149.91,1049
NetP2_14: P2.14 R93.1 | length 64.5
  TOP w6: P2.14@249.91,1049 R93.1@314.38,1049
NetP2_15: P2.15 R96.2 | length 89.1
  TOP w6: R96.2@71.62,975 78.43,975 104.43,949 P2.15@149.91,949
NetP2_16: P2.16 R97.1 | length 63.5
  TOP w6: P2.16@249.91,949 R97.1@313.38,949
NetP2_17: P2.17 R98.2 R108.2 R110.2 | length 534.8
  TOP w6: R108.2@71.62,800 R98.2@71.62,843 77.62,849 P2.17@149.91,849 ; R110.2@476,735 v2(476,769.54)
  PWR w6: P2.17@149.91,849 204.22,794.69 295.05,794.69 316.18,815.83 429.72,815.83 v2(476,769.54)
NetP2_18: P2.18 R99.1 | length 65.5
  TOP w6: P2.18@249.91,849 R99.1@315.38,849
NetP2_19: P2.19 R100.2 R109.2 R111.2 | length 186.3
  TOP w6: R111.2@24.21,689.13 R109.2@70.4,689.13 71.62,690.35 R100.2@71.62,750 72.62,749 P2.19@149.91,749
NetP2_20: P2.20 R101.1 R106.1 | length 111.5
  TOP w6: P2.20@249.91,749 R106.1@316.38,749 R101.1@316.38,704
NetQ1_3: Q1.3 R20.1 | length 136.6
  TOP w8: R20.1@1202,3703.5 1249.58,3703.5 1307,3646.08 Q1.3@1307,3638.24
NetQ2_1: Q2.1 R155.1 | length 58
  TOP w15.01: R155.1@1918.92,2856.2 1921.33,2853.79 Q2.1@1975.9,2853.79
NetQ2_2: Q2.2 Q2.5 Q3.1 R153.1 SW4.2 | length 726.7
  TOP w10: Q3.1@1901.61,2712.52 1918.92,2729.83 R153.1@1918.92,2796.2 1950.92,2828.2 Q2.2@1975.9,2828.2 Q2.5@2050.7,2828.2 2079.09,2828.2 2093.93,2813.36 2093.93,2440.42 SW4.2@2142.4,2391.95
NetQ2_4: Q2.4 R154.1 | length 73.4
  TOP w6: R154.1@2050.7,2729.21 Q2.4@2050.7,2802.61
NetQ4_1: Q4.1 R165.2 | length 469.2
  TOP w6: R165.2@1529.06,334.21 v2(1559.21,334.21) ; Q4.1@1938.7,245.07 v2(1938.7,283.7)
  PWR w6: v2(1559.21,334.21) 1850.82,334.21 1901.34,283.7 v2(1938.7,283.7)
NetQ4_3: Q4.3 R162.1 | length 362.8
  TOP w20: R162.1@1630,87.2 1630,150 1665,185 1745,185 1779.42,150.58 Q4.3@1901.3,150.58
NetQ5_1: Q5.1 R167.2 | length 294.2
  TOP w6: R167.2@1529.06,379.21 1569.21,379.21 1593.2,355.22 1593.2,288.15 1607.13,274.22 1692.15,274.22 Q5.1@1726.3,240.07
NetQ5_3: Q5.3 R163.1 | length 76.6
  TOP w20: Q5.3@1688.9,145.58 1688.9,77.6 R163.1@1695,71.5
NetQ6_1: Q6.1 R172.2 | length 57.1
  TOP w20: R172.2@1792.2,244.69 Q6.1@1792.2,301.82
NetQ7_1: Q7.1 R168.2 | length 267.2
  TOP w6: v2(1523.08,240.07) Q7.1@1558.9,240.07 ; R168.2@1529.06,419.21 v2(1564.21,419.21)
  BOTTOM w6: v2(1523.08,240.07) 1523.08,378.08 v2(1564.21,419.21)
NetQ7_3: Q7.3 R164.1 | length 72.2
  TOP w20: R164.1@1493.5,85 1521.49,112.99 Q7.3@1521.49,145.58
NetR2_1: R2.1 U1.1 | length 89.4
  TOP w15: U1.1@1124.61,606.65 R2.1@1213.97,606.65
NetR5_2: R5.2 U3.33 | length 148.6
  TOP w6: U3.33@902.15,2840.91 924.09,2840.91 928.38,2836.62 R5.2@928.38,2716
NetR6_2: R6.2 U3.95 | length 218.4
  TOP w6: R6.2@227.62,3526 264,3526 370.65,3419.35 U3.95@370.65,3388.15
NetR7_2: R7.2 U3.34 | length 127.3
  TOP w6: U3.34@902.15,2856.65 929.15,2856.65 942,2843.8 942,2800 966,2776 R7.2@970.38,2776
NetR9_2: R9.2 U3.35 | length 94.2
  TOP w6: U3.35@902.15,2872.4 933.86,2872.4 957,2849.26 957,2838.38 R9.2@970.38,2825
NetR10_2: R10.2 U3.36 | length 72
  TOP w6: U3.36@902.15,2888.15 961.23,2888.15 R10.2@970.38,2879
NetR11_2: R11.2 U3.37 | length 78.2
  TOP w6: U3.37@902.15,2903.9 942.9,2903.9 967,2928 R11.2@970.38,2928
NetR12_2: R12.2 U3.38 | length 104.7
  TOP w6: U3.38@902.15,2919.65 934.65,2919.65 943.63,2928.63 943.63,2942.96 954.71,2954.05 954.71,2961.33 R12.2@970.38,2977
NetR13_1: R13.1 U4.4 | length 585.1
  TOP w8: R13.1@1017.62,3025 1052.76,3025 1136.29,3108.53 U4.4@1136.29,3540.41
NetR13_2: R13.2 U3.40 | length 118.5
  TOP w6: U3.40@902.15,2951.14 930.14,2951.14 942.71,2963.71 942.71,2997.33 R13.2@970.38,3025
NetR14_2: R14.2 R17.2 U4.3 | length 91.7
  TOP w6: R17.2@1047.71,3448.69 R14.2@1047.71,3496.62 U4.3@1047.71,3540.41
NetR21_2: R21.2 SW1.3 | length 146.9
  TOP w6: SW1.3@880.05,3823.02 R21.2@1027,3823.02
NetR22_2: R22.2 U3.63 | length 148
  TOP w6: U3.63@902.15,3313.35 930.98,3313.35 940,3322.37 940,3378.24 R22.2@975.76,3414
NetR23_2: R23.2 U3.62 | length 120.7
  TOP w6: U3.62@902.15,3297.6 940.6,3297.6 954.63,3311.63 954.63,3336.25 R23.2@981.38,3363
NetR24_2: R24.2 U3.61 | length 91.3
  TOP w6: U3.61@902.15,3281.85 952.23,3281.85 R24.2@981.38,3311
NetR25_2: R25.2 U3.60 | length 81.8
  TOP w6: U3.60@902.15,3266.1 975.28,3266.1 R25.2@981.38,3260
NetR26_2: R26.2 R29.2 U3.70 | length 333.2
  TOP w6: R29.2@704.38,3660 R26.2@704.38,3607 704.38,3566.38 690,3552 690,3452 712,3430 754,3430 764.35,3419.65 U3.70@764.35,3388.15
NetR30_2: R30.2 U3.59 | length 101.8
  TOP w6: U3.59@902.15,3250.35 937.65,3250.35 983.5,3204.5 R30.2@983.5,3203
NetR34_1: R34.1 U7.4 | length 69.5
  TOP w6: R34.1@1305.22,3413.41 1310.2,3408.43 U7.4@1310.2,3346
NetR36_2: R36.2 U8.3 | length 66.9
  TOP w6: R36.2@1359.98,3202.41 1359.6,3202.03 1359.6,3159.41 1370.01,3149 U8.3@1379,3149
NetR49_2: R49.2 U10.23 | length 229.4
  TOP w6: R49.2@942.12,881.02 937.7,885.45 937.7,1016.17 966.98,1045.45 966.98,1055.52 990.47,1079 U10.23@990.47,1086.77
NetR114_1: R114.1 U11.8 U11.9 | length 201
  TOP w6: R114.1@262.62,2165 284,2165 295.82,2153.18 388.18,2153.18 394.51,2159.51 394.51,2169.61 385.35,2178.77 U11.8@346.8,2178.77
NetR115_2: R115.2 R118.2 U11.10 | length 139.4
  TOP w6: R118.2@262.62,2065 R115.2@262.62,2115 289,2115 301.59,2127.59 U11.10@346.8,2127.59
NetR116_1: R116.1 U11.6 U11.7 | length 206.6
  TOP w6: U11.6@571.2,2153.18 530.82,2153.18 524,2160 524,2170 532.77,2178.77 661.61,2178.77 R116.1@665.38,2175
NetR117_2: R117.2 R119.2 U11.5 | length 145.2
  TOP w6: U11.5@571.2,2127.59 662.79,2127.59 R117.2@665.38,2125 R119.2@665.38,2075
NetR122_1: R122.1 U11.1 U11.2 | length 200.5
  TOP w6: U11.2@571.2,2050.82 532.02,2050.82 527.11,2045.91 527.11,2030.51 532.4,2025.23 598.2,2025.23 606.62,2016.8 606.62,1973.16 R122.1@613.82,1965.96
NetR124_1: R124.1 U11.13 U11.14 | length 170.9
  TOP w6: R124.1@335.38,1965 335.38,1991.38 346.8,2002.8 U11.14@346.8,2025.23 384.73,2025.23 389.91,2030.41 389.91,2045.91 385.01,2050.82 U11.13@346.8,2050.82
NetR126_2: R126.2 R128.2 U11.3 | length 207.6
  TOP w6: U11.3@571.2,2076.41 600.49,2076.41 618.63,2058.27 618.63,2021.75 R126.2@665.38,1975 R128.2@665.38,1925
NetR127_2: R127.2 R129.2 U11.12 | length 166.1
  TOP w6: R129.2@262.62,1965 R127.2@262.62,2015 294,2046.38 294,2057.47 312.94,2076.41 U11.12@346.8,2076.41
NetR137_1: R137.1 R140.2 U13.1 | length 113.4
  TOP w8: R137.1@171,170.24 171.76,171 R140.2@221,171 221,165.72 223.91,162.81 U13.1@223.91,109.15
NetR138_1: R138.1 R144.2 U12.4 | length 125.1
  TOP w10: R144.2@542.54,196.35 573.74,165.16 ; U12.4@560.72,87.35 560.72,89.22 573.74,102.24 573.74,162.92
NetR141_1: R141.1 U13.5 | length 512.6
  TOP w6: U13.5@246.16,47.54 246.16,19.78 247,20.62 v2(247,21.62) ; v2(629.63,175.34) R141.1@629.63,211.68
  BOTTOM w6: v2(247,21.62) 395.91,21.62 549.63,175.34 v2(629.63,175.34)
NetR145_2: R145.2 U13.2 | length 140.6
  TOP w6: v2(122,96) R145.2@122,132 ; v2(197,96) 203.54,89.46 U13.2@223.91,89.46
  BOTTOM w6: v2(122,96) v2(197,96)
NetR146_1: R146.1 U13.11 | length 103.7
  TOP w8: U13.11@265.84,111.71 265.84,122.46 271.39,128.02 317,128.02 317,127.62 329.38,115.24 R146.1@351,115.24
NetR147_2: R147.2 U13.12 | length 69.6
  TOP w8: U13.12@246.16,111.71 246.16,126.78 271,151.62 R147.2@271,171
NetR148_2: R148.2 U12.6 | length 56.4
  TOP w10: R148.2@456.69,78.74 483.87,78.74 492.48,87.35 U12.6@509.54,87.35
NetR149_2: R149.2 U12.1 | length 63
  TOP w10: R149.2@456.69,39.37 479.02,39.37 U12.1@507.81,10.58
NetR150_2: R150.2 SW2.4 | length 155.9
  TOP w6: R150.2@-20.62,1719 -20.62,1744.08 34.98,1799.69 SW2.4@34.98,1851.92
NetR151_2: R151.2 SW3.4 | length 111.9
  TOP w6: SW3.4@2065.02,2017.27 R151.2@2065.02,2129.21
NetR159_2: R159.2 SW4.1 | length 244.2
  TOP w10: R159.2@1960.07,2172.83 2102.47,2172.83 2142.4,2212.76 SW4.1@2142.4,2258.1
NetR161_1: R161.1 U14.8 | length 207.1
  TOP w8: U14.8@1697.4,3567.53 1710,3580.13 1710,3593.66
  TOP w15.01: 1710,3593.66 1710,3604.21 1726.44,3620.66 1788.11,3620.66 1837,3571.77 R161.1@1837,3560.62
P01_GPIO_10: J11.9 R68.1 R98.1 R132.1 R167.1 R170.1 U10.1 | length 5728.8
  TOP w6: v2(-11.96,843) R98.1@24.38,843 ; v2(79,1482) 92,1495 290,1495 311.81,1516.81 676.61,1516.81 735.43,1458 v2(787,1458) 837.36,1407.64 U10.1@846.77,1407.64 ; v2(343.38,641.52) R132.1@378.76,641.52 ; v1(1059,2103.51) J11.9@1059,2175.43 ; v2(1069.21,1774.21) 1237.45,1774.21 1350.8,1887.56 1523.73,1887.56 1549.21,1862.08 1549.21,1680.09 1630.56,1598.73 1630.56,1573.98 1654.54,1550 R68.1@1716.38,1550 ; v2(1430.43,379.21) R167.1@1481.81,379.21 ; v2(1739.21,79.21) R170.1@1767.85,79.21
  PWR w6: v2(79,1482) 79,1150.92 -17.79,1054.13 -17.79,997.17 -11.96,991.34 v2(-11.96,843) -1.72,832.76 -1.72,822.37 157.33,663.33 268.95,663.33 290.76,641.52 v2(343.38,641.52) ; v2(1430.43,379.21) 1430.43,297.99 1649.21,79.21 v2(1739.21,79.21)
  BOTTOM w6: v2(343.38,641.52) 393.38,641.52 418.42,616.48 557.91,616.48 679.41,494.98 728.97,494.98 836.83,387.12 904.53,387.12 906.92,389.51 1066.73,389.51 1069.12,387.12 1080.82,387.12 1083.45,384.5 1203.19,384.5 1222,403.31 1406.34,403.31 v2(1430.43,379.21) ; v2(787,1458) 787,1508.06 870,1591.06 870,1678 897.65,1705.65 1000.65,1705.65 v2(1069.21,1774.21) 1101.72,1806.72 1101.72,1859.62 1070.27,1891.07 1036.97,1891.07 1023.98,1904.06 1023.98,2068.49 v1(1059,2103.51)
P02_GPIO_11: J11.11 R67.1 R100.1 R139.1 R165.1 R169.1 U10.2 | length 5916.2
  TOP w6: v2(-1.21,728.35) 20.44,750 R100.1@24.38,750 ; v2(572.24,564.21) R139.1@572.24,592.52 ; v2(765,1425) 787.68,1425 824.73,1387.95 U10.2@846.77,1387.95 ; v1(1009,2103.51) J11.11@1009,2175.43 ; v2(1069.21,1814.21) 1260.48,1814.21 1345.83,1899.56 1529.44,1899.56 1564.21,1864.79 1564.21,1729.83 1631.83,1662.21 1712.59,1662.21 R67.1@1715.59,1659.21 ; v2(1449.21,344.21) 1459.21,334.21 R165.1@1481.81,334.21 ; v2(1901.3,241.11) 1924.21,218.2 1924.21,93.18 R169.1@1910.25,79.21
  PWR w6: v2(24.21,1299.61) 6.38,1281.77 6.38,1258.24 14.33,1250.28 14.33,1129.69 -39.79,1075.57 -39.79,1072.51 -39.96,1072.34 -39.96,767.09 v2(-1.21,728.35) -1.21,609.64 14.21,594.21 215.79,594.21 289.91,520.09 528.12,520.09 v2(572.24,564.21) ; v2(1449.21,344.21) 1509.21,284.21 1858.2,284.21 v2(1901.3,241.11)
  BOTTOM w6: v2(24.21,1299.61) 24.61,1300 457,1300 568,1411 751,1411 v2(765,1425) 765,1505.93 847,1587.93 847,1682 883.48,1718.48 973.48,1718.48 v2(1069.21,1814.21) 1084.75,1829.75 1084.75,1854.1 1065.54,1873.31 1027.68,1873.31 1009,1891.99 v1(1009,2103.51) ; v2(572.24,564.21) 617.99,518.47 617.99,453.94 637.46,434.47 671.45,434.47 765.32,340.59 873.55,340.59 911.47,378.51 1062.18,378.51 1073.1,367.59 1418.01,367.59 1441.39,344.21 v2(1449.21,344.21)
P03_GPIO_12: R80.1 R110.1 R136.1 U10.3 | length 2007.4
  TOP w6: R80.1@24.38,1356 v2(24.38,1394.05) 39.21,1394.05 45.17,1400 382,1400 480,1498 656,1498 753,1401 784.1,1401 816.83,1368.27 U10.3@846.77,1368.27 ; R136.1@428.76,689.21 v2(428.76,769.54)
  BOTTOM w6: v2(24.38,1394.05) -4.34,1365.33 -4.34,1172.82 85.23,1083.25 85.23,850.17 131.19,804.21 370.79,804.21 405.46,769.54 v2(428.76,769.54)
P04_GPIO_13: R76.1 R111.1 R141.2 R143.1 R156.1 SW2.3 U10.4 | length 3648
  TOP w6: v2(24.21,614.21) R111.1@24.21,641.89 ; R143.1@572.83,529.21 589.65,512.39 589.65,504.86 v2(600.31,494.21) 600.31,317.99 R141.2@626.61,291.68 ; R141.2@620.52,291.68 R141.2@626.61,291.68 ; R141.2@629.63,291.68 R141.2@626.61,291.68 ; 745,1385 780.3,1385 816.72,1348.58 U10.4@846.77,1348.58
  TOP w8: R156.1@-36.62,2150 34.98,2078.4 SW2.3@34.98,2017.27 44.2,2017.27 77.25,1984.22 77.25,1691.25 -10,1604 -10,1499 24.38,1464.62 R76.1@24.38,1441 -7.89,1408.73 -7.89,1341.02 11.42,1321.71 v2(59.21,1321.71) 75.29,1321.71 97,1300 375.7,1300 520.01,1444.31 672.69,1444.31 732,1385 745,1385
  PWR w6: v2(59.21,1321.71) 59.21,1155.95 -28.96,1067.78 -28.96,792.96 24.21,739.79 v2(24.21,614.21) 231.18,614.21 293.82,551.57 432.47,551.57 462.11,581.21 579.29,581.21 600.31,560.19 v2(600.31,494.21)
P05_GPIO_14: R92.1 U10.5 | length 1169.5
  TOP w6: R92.1@24.53,1069.21 19.21,1069.21 -29.89,1118.31 -29.89,1155.57 -14.32,1171.14 100.55,1171.14 123.25,1193.84 353.98,1193.84 461.02,1300.89 461.02,1355.32 527.7,1422 643.7,1422 700.49,1365.21 780.29,1365.21 816.61,1328.9 U10.5@846.77,1328.9
P06_GPIO_15: R83.2 R104.2 U10.6 | length 2075.7
  TOP w6: v2@819,1309.81 846.17,1309.81 U10.6@846.77,1309.21 ; v2(2000,1200) 2000,1214 2014,1228 2072,1228 2078.9,1221.1 2078.9,1200 2110,1200 2133,1177 2133,1093.81 2089.19,1050 R83.2@2083.62,1050
  BOTTOM w6: v2(819,1309.21) 819,1046 834.83,1030.17 964.41,1030.17 989.76,1055.52 1052.18,1055.52 1078.6,1029.1 1078.6,988.23 1106.5,960.34 1139.27,960.34 1194.4,905.22 1202.82,905.22 1202.97,905.06 1314.44,905.06 1356.11,946.73 1647.74,946.73 1801.02,1100 1970,1100 2000,1130 v2(2000,1200)
P07_GPIO_16: R79.2 R105.2 U10.7 | length 2373.9
  TOP w6: v2(701,1337) 713.21,1349.21 750.12,1349.21 809.8,1289.53 U10.7@846.77,1289.53 ; R105.2@2083.62,1100 R79.2@2083.62,1150 v2(2112,1150)
  BOTTOM w6: v2(701,1337) 664.87,1300.87 664.87,1189.13 745,1109 745,1046.35 934.61,856.74 954.2,856.74 1013.21,797.73 1124.49,797.73 1180.47,741.75 1231.2,741.75 1272.64,783.18 1272.64,810.77 1293.03,831.17 1307.48,831.17 1330.5,808.14 1472.73,808.14 1534.59,870 1652.37,870 1682.47,900.1 2004.91,900.1 2112,1007.2 v2(2112,1150)
P08_GPIO_17: R71.2 U10.8 | length 2314.6
  TOP w6: v2(741,1326) 756.05,1326 805.24,1276.81 814,1276.81 820.97,1269.84 U10.8@846.77,1269.84 ; R71.2@2079.7,1450 v2(2107.08,1450)
  BOTTOM w6: v2(741,1326) 741,1273 800,1214 800,1043.07 916.59,926.48 996.95,926.48 1030.81,892.62 1176.56,892.62 1178.16,894.22 1198.26,894.22 1252.63,839.85 1270.55,839.85 1341.34,910.64 1343.8,910.64 1360.28,927.12 1737.13,927.12 1805,995 2000,995 2081.7,1076.69 2081.7,1420.61 v2@2111.08,1450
